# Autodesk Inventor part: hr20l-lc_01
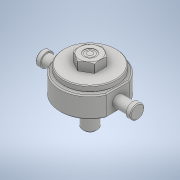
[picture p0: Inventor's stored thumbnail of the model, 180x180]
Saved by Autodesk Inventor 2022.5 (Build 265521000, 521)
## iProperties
Part Number: hr20l-lc_01
Material: 一般
Document SubType Name: Modeling
Designer: ImaoCorp
Density: 1 g/cm^3
Appearance: 既定
Author: ImaoCorp
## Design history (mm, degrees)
feature "hr20l-lc_01"
node "ソリッド1"
